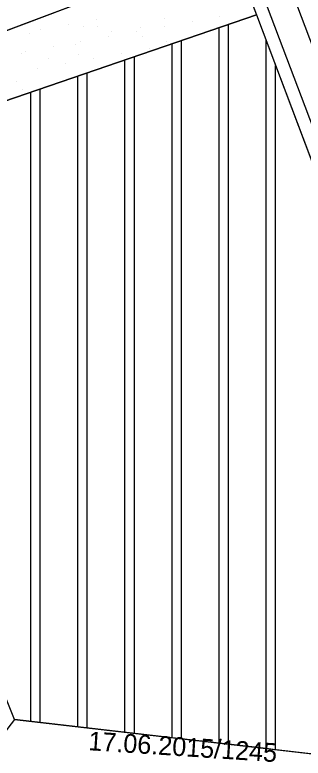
# Model space of a CAD drawing. Extents: x 409341 to 428634, y 4447481 to 4463281.
# Drawn here: x 419718.9 to 419872, y 4459294.6 to 4459689.8 of the extents above; entities that cross this region are included whole.
import ezdxf

# ---------------------------------------------------------------- set-up
doc = ezdxf.new("R2010")
doc.units = 0
for name, color, linetype in [('ADA', 7, 'Continuous'), ('ADAKENARI', 7, 'Continuous'), ('Default', 7, 'Continuous'), ('KALDIRIM', 7, 'Continuous'), ('PL_AYA_PARK_DINLENME', 7, 'Continuous'), ('PL_K_ASKERI_ALAN', 7, 'Continuous'), ('PL_SAY_YUKSEK_UNIVER', 7, 'Continuous'), ('TR_ASKERIALAN', 7, 'Continuous'), ('TR_PARKALANI', 7, 'Continuous'), ('YÜRÜTMEYİ_DURDURMA', 7, 'Continuous')]:
    doc.layers.add(name, color=color, linetype=linetype)

# ---------------------------------------------------------------- blocks, each defined once
blk = doc.blocks.new('POINT_DISPLAY')
at = {"layer": 'Default'}
blk.add_line((0, 0), (0, 0), dxfattribs=at)

msp = doc.modelspace()

# ---------------------------------------------------------------- linework, layer by layer
at = {"layer": 'ADA'}
for p, q in [((419602.34, 4459605.86), (419847.21, 4459689.72)), ((419718.68, 4459315.02), (419886.72, 4459295.63))]:
    msp.add_line(p, q, dxfattribs=at)
at = {"layer": 'ADAKENARI'}
for p, q in [((419588.57, 4459634.05), (419824.03, 4459722.86)), ((419836.92, 4459717.03), (419847.21, 4459689.72)), ((419847.21, 4459689.72), (419981.1, 4459334.68))]:
    msp.add_line(p, q, dxfattribs=at)
at = {"layer": 'KALDIRIM'}
for p, q in [((420196.04, 4458827.01), (419860.78, 4459716.11)), ((420196.04, 4458827.01), (419860.78, 4459716.11)), ((420170.33, 4458852.66), (419849.91, 4459702.42)), ((420171.87, 4458848.59), (419849.91, 4459702.42)), ((420170.33, 4458852.66), (419849.91, 4459702.42)), ((420171.87, 4458848.59), (419849.91, 4459702.42))]:
    msp.add_line(p, q, dxfattribs=at)
at = {"layer": 'PL_AYA_PARK_DINLENME'}
msp.add_lwpolyline([(419588.57, 4459634.05), (419824.03, 4459722.86), (419836.92, 4459717.03), (419847.21, 4459689.72), (419602.34, 4459605.86)], close=True, dxfattribs=at)
at = {"layer": 'PL_K_ASKERI_ALAN'}
msp.add_lwpolyline([(419886.72, 4459295.63), (419718.68, 4459315.02), (419602.34, 4459605.86), (419847.21, 4459689.72), (419981.1, 4459334.68)], close=True, dxfattribs=at)
at = {"layer": 'PL_SAY_YUKSEK_UNIVER'}
msp.add_lwpolyline([(419877.34, 4459296.71), (419857.34, 4459299.02), (419852.34, 4459299.6), (419832.34, 4459301.9), (419827.34, 4459302.48), (419807.34, 4459304.79), (419802.34, 4459305.37), (419782.34, 4459307.67), (419777.34, 4459308.25), (419757.34, 4459310.56), (419752.34, 4459311.13), (419732.34, 4459313.44), (419727.34, 4459314.02), (419718.68, 4459315.02), (419715.2, 4459310.44), (419710.49, 4459304.24), (419707.6, 4459300.44), (419700.49, 4459291.07)], dxfattribs=at)
at = {"layer": 'TR_ASKERIALAN'}
for p, q in [((419827.34, 4459302.48), (419827.34, 4459682.92)), ((419832.34, 4459301.9), (419832.34, 4459684.63)), ((419802.34, 4459305.37), (419802.34, 4459674.36)), ((419807.34, 4459304.79), (419807.34, 4459676.07)), ((419852.34, 4459299.6), (419852.34, 4459676.13)), ((419777.34, 4459308.25), (419777.34, 4459665.8)), ((419782.34, 4459307.67), (419782.34, 4459667.51)), ((419857.34, 4459299.02), (419857.34, 4459662.87)), ((419752.34, 4459311.13), (419752.34, 4459657.23)), ((419757.34, 4459310.56), (419757.34, 4459658.95)), ((419732.34, 4459313.44), (419732.34, 4459650.38)), ((419727.34, 4459314.02), (419727.34, 4459648.67))]:
    msp.add_line(p, q, dxfattribs=at)

# ---------------------------------------------------------------- block references
at = {"layer": 'TR_PARKALANI', "xscale": 0.1, "yscale": 0.10000000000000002}
for p in [(419762.07, 4459687.23), (419762.07, 4459687.23), (419798.34, 4459687.71), (419813.05, 4459686.06), (419813.05, 4459686.06), (419827.82, 4459688.67), (419827.82, 4459688.67), (419732.53, 4459682.02), (419732.53, 4459682.02), (419747.3, 4459684.62), (419747.3, 4459684.62), (419755.18, 4459683.6), (419762.5, 4459683.75), (419769.95, 4459681), (419785.59, 4459683.32), (419798.28, 4459683.46), (419798.28, 4459683.46), (419822.68, 4459682.03), (419822.68, 4459682.03), (419726.66, 4459679.78), (419768.74, 4459678.25), (419768.74, 4459678.25), (419783.51, 4459680.85), (419783.51, 4459680.85), (419786.85, 4459678.07), (419786.85, 4459678.07), (419739.19, 4459673.04), (419739.19, 4459673.04), (419751.01, 4459674.11), (419751.01, 4459674.11), (419753.96, 4459675.64), (419753.96, 4459675.64), (419799.5, 4459675.79), (419722.16, 4459669.11), (419724.42, 4459670.43), (419724.42, 4459670.43), (419775.4, 4459669.27), (419775.4, 4459669.27), (419790.17, 4459671.87), (419790.17, 4459671.87), (419736.94, 4459666.51), (419752.58, 4459668.83), (419760.62, 4459666.66), (419760.62, 4459666.66), (419731.08, 4459661.46), (419731.08, 4459661.46), (419745.85, 4459664.06), (419745.85, 4459664.06), (419719.56, 4459654.34), (419722.97, 4459649.87), (419722.97, 4459649.87), (419737.74, 4459652.48), (419737.74, 4459652.48)]:
    msp.add_blockref('POINT_DISPLAY', p, dxfattribs=at)

# ---------------------------------------------------------------- texts
at = {"layer": 'YÜRÜTMEYİ_DURDURMA'}
msp.add_text('17.06.2015/1245', height=10, rotation=356.3481, dxfattribs=at).set_placement((419757.67, 4459298.79))

doc.saveas('drawing.dxf')
